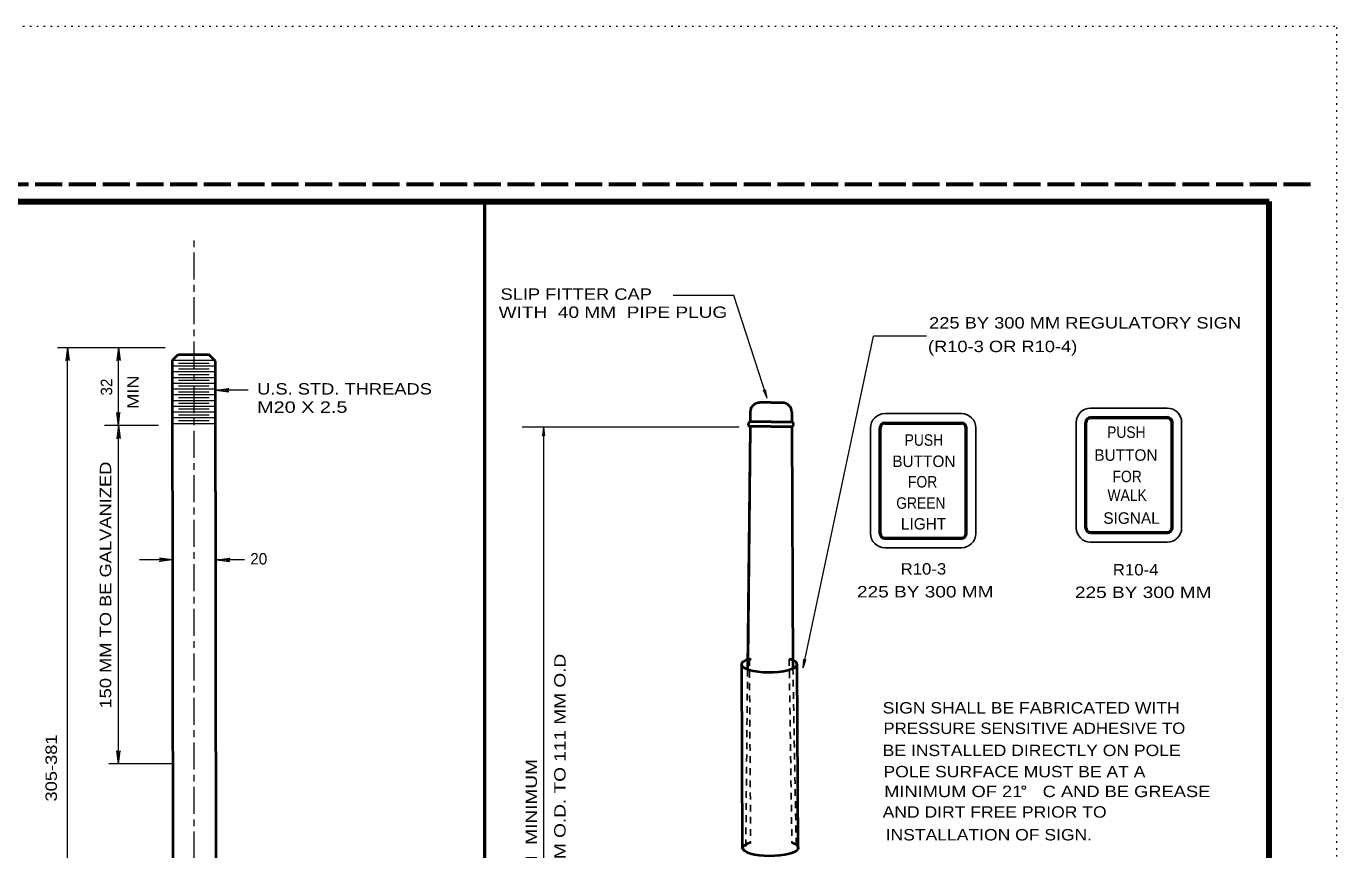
# Model space of a CAD drawing. Extents: x 312583 to 312854, y 144419 to 144597.
# Drawn here: x 312766.1 to 312853.5, y 144541.9 to 144596.8 of the extents above; entities that cross this region are included whole.
import ezdxf
from ezdxf.enums import TextEntityAlignment as Align

# ---------------------------------------------------------------- set-up
doc = ezdxf.new("R2010")
doc.units = 0
doc.header["$LTSCALE"] = 0.3
for name, pattern in [('DOTTED', [1.5, 0.3, -1.2]), ('LONG_DASH_SHORT_DASH', [9.9, 6, -1.2, 1.5, -1.2]), ('LONG_DASHED', [7.5, 6, -1.5]), ('SHORT_DASHED', [2.7, 1.5, -1.2])]:
    doc.linetypes.add(name, pattern=pattern)
for name, color, linetype, lineweight in [('1', 7, 'Continuous', 40), ('2', 7, 'Continuous', 13), ('62', 7, 'DOTTED', 13), ('63', 7, 'LONG_DASHED', 60)]:
    doc.layers.add(name, color=color, linetype=linetype, lineweight=lineweight)

msp = doc.modelspace()

# ---------------------------------------------------------------- linework, layer by layer
at = {"layer": '1', "lineweight": 53}
for p, q in [((312796.6723, 144460.1131), (312796.6723, 144585.0846)), ((312837.0869, 144570.6839), (312842.1929, 144570.6839)), ((312823.0385, 144562.9616), (312823.0385, 144569.9919)), ((312823.3605, 144570.3063), (312828.4741, 144570.3063)), ((312828.7885, 144562.9616), (312828.7885, 144569.9919)), ((312836.7649, 144563.3315), (312836.7649, 144570.3619)), ((312842.5149, 144563.3315), (312842.5149, 144570.3619)), ((312837.0869, 144563.0172), (312842.1929, 144563.0172)), ((312823.3605, 144562.6396), (312828.4741, 144562.6396))]:
    msp.add_line(p, q, dxfattribs=at)
at = {"layer": '1', "lineweight": 158}
msp.add_line((312849, 144423.1446), (312849, 144585.0846), dxfattribs=at)
at = {"layer": '1', "linetype": 'LONG_DASH_SHORT_DASH', "lineweight": 13}
msp.add_line((312777.2876, 144511.5796), (312777.2876, 144582.5116), dxfattribs=at)
at = {"layer": '1'}
for p, q in [((312775.8463, 144574.5153), (312776.2296, 144574.8986)), ((312775.9153, 144519.9976), (312775.8463, 144574.5153)), ((312776.2296, 144574.8986), (312778.269, 144574.8986)), ((312778.7213, 144574.4463), (312778.269, 144574.8986)), ((312778.7826, 144520.2276), (312778.7213, 144574.4463)), ((312815.7682, 144571.6786), (312815.0168, 144571.6786)), ((312815.7682, 144571.6786), (312816.5195, 144571.6786)), ((312814.3805, 144571.0423), (312814.3728, 144570.3906)), ((312817.1558, 144571.0423), (312817.1635, 144570.3906)), ((312814.3728, 144570.0839), (312814.2042, 144553.8766)), ((312814.3728, 144570.0839), (312814.2042, 144553.9609)), ((312814.3728, 144570.0839), (312814.2042, 144553.8996)), ((312814.3728, 144570.0839), (312814.2118, 144554.4593)), ((312815.7682, 144570.3983), (312814.3728, 144570.3983)), ((312815.7682, 144570.0839), (312814.3728, 144570.0839)), ((312815.7682, 144570.0839), (312814.3728, 144570.0839)), ((312815.7682, 144570.0839), (312814.3728, 144570.0839)), ((312815.7682, 144570.0839), (312814.3728, 144570.0839)), ((312815.7682, 144570.0839), (312814.3728, 144570.0839)), ((312815.7682, 144570.0839), (312814.3728, 144570.0839)), ((312815.7682, 144570.0839), (312814.3728, 144570.0839)), ((312815.7682, 144570.0839), (312814.3728, 144570.0839)), ((312815.7682, 144570.3983), (312817.1635, 144570.3983)), ((312815.7682, 144570.0839), (312817.1635, 144570.0839)), ((312815.7682, 144570.0839), (312817.1635, 144570.0839)), ((312815.7682, 144570.0839), (312817.1635, 144570.0839)), ((312815.7682, 144570.0839), (312817.1635, 144570.0839)), ((312815.7682, 144570.0839), (312817.1635, 144570.0839)), ((312815.7682, 144570.0839), (312817.1635, 144570.0839)), ((312815.7682, 144570.0839), (312817.1635, 144570.0839)), ((312815.7682, 144570.0839), (312817.1635, 144570.0839)), ((312817.1635, 144570.0839), (312817.2325, 144553.9993)), ((312813.7902, 144554.1679), (312813.8515, 144541.9089)), ((312814.3268, 144554.5819), (312814.4495, 144554.6049)), ((312817.0792, 144554.5589), (312816.9795, 144554.5743)), ((312817.4932, 144554.1833), (312817.5622, 144541.9396))]:
    msp.add_line(p, q, dxfattribs=at)
at = {"layer": '1', "lineweight": 13}
for p, q in [((312775.8463, 144574.5153), (312778.7213, 144574.5153)), ((312776.2526, 144574.3236), (312778.292, 144574.3236)), ((312775.8463, 144574.1319), (312778.7213, 144574.1319)), ((312775.8463, 144573.7486), (312778.7213, 144573.7486)), ((312775.8463, 144573.3653), (312778.7213, 144573.3653)), ((312776.2526, 144573.9403), (312778.292, 144573.9403)), ((312776.2526, 144573.5569), (312778.292, 144573.5569)), ((312775.8463, 144572.9819), (312778.7213, 144572.9819)), ((312775.8463, 144572.5986), (312778.7213, 144572.5986)), ((312776.2526, 144573.1736), (312778.292, 144573.1736)), ((312776.2526, 144572.7903), (312778.292, 144572.7903)), ((312775.8463, 144572.2153), (312778.7213, 144572.2153)), ((312775.8463, 144571.8319), (312778.7213, 144571.8319)), ((312776.2526, 144572.4069), (312778.292, 144572.4069)), ((312776.2526, 144572.0236), (312778.292, 144572.0236)), ((312776.2526, 144571.6403), (312778.292, 144571.6403)), ((312775.8463, 144571.4486), (312778.7213, 144571.4486)), ((312775.8463, 144571.0653), (312778.7213, 144571.0653)), ((312775.8463, 144570.6819), (312778.7213, 144570.6819)), ((312776.2526, 144571.2569), (312778.292, 144571.2569)), ((312776.2526, 144570.8736), (312778.292, 144570.8736)), ((312775.8463, 144570.2986), (312778.7213, 144570.2986)), ((312776.2526, 144570.4903), (312778.292, 144570.4903))]:
    msp.add_line(p, q, dxfattribs=at)
at = {"layer": '1', "lineweight": 25}
for p, q in [((312823.3605, 144570.9503), (312828.4741, 144570.9503)), ((312837.0869, 144571.3202), (312842.1929, 144571.3202)), ((312822.4021, 144562.9616), (312822.4021, 144569.9919)), ((312829.4325, 144562.9616), (312829.4325, 144569.9919)), ((312843.1512, 144563.3315), (312843.1512, 144570.3619)), ((312823.3605, 144562.0033), (312828.4741, 144562.0033)), ((312837.0869, 144562.3732), (312842.1929, 144562.3732))]:
    msp.add_line(p, q, dxfattribs=at)
at = {"layer": '1', "linetype": 'SHORT_DASHED', "lineweight": 25}
for p, q in [((312814.3268, 144554.5819), (312814.4112, 144542.3459)), ((312816.9795, 144554.5743), (312817.1635, 144542.3229)), ((312814.2042, 144553.8766), (312814.0815, 144541.7786)), ((312817.2325, 144553.9993), (312817.4548, 144541.7939))]:
    msp.add_line(p, q, dxfattribs=at)
at = {"layer": '1', "lineweight": 158}
msp.add_lwpolyline([(312616.5, 144423.1446), (312616.5, 144585.0846), (312849, 144585.0846)], dxfattribs=at)
at = {"layer": '1'}
for centre, start, end in [((312815.0188, 144571.0384), 90, 179.43048), ((312816.5162, 144571.0384), 0.56952, 90)]:
    msp.add_arc(centre, 0.6389, start, end, dxfattribs=at)
at = {"layer": '1', "lineweight": 25}
for centre, start, end in [((312823.3598, 144569.99), 90, 180), ((312828.4709, 144569.99), 0, 90), ((312837.0837, 144570.3612), 90, 180), ((312842.1948, 144570.3612), 0, 90), ((312823.3598, 144562.9622), 180, 270), ((312828.4709, 144562.9622), 270, 0), ((312837.0837, 144563.3335), 180, 270), ((312842.1948, 144563.3335), 270, 0)]:
    msp.add_arc(centre, 0.9583, start, end, dxfattribs=at)
at = {"layer": '1', "lineweight": 53}
for centre, start, end in [((312837.0837, 144570.3612), 90, 180), ((312842.1948, 144570.3612), 0, 90), ((312823.3598, 144569.99), 90, 180), ((312828.4709, 144569.99), 0, 90), ((312823.3598, 144562.9622), 180, 270), ((312828.4709, 144562.9622), 270, 0), ((312837.0837, 144563.3335), 180, 270), ((312842.1948, 144563.3335), 270, 0)]:
    msp.add_arc(centre, 0.3194, start, end, dxfattribs=at)
at = {"layer": '1'}
for centre in [(312815.6522, 144554.2219), (312815.7372, 144541.984)]:
    msp.add_ellipse(centre, major_axis=(1.8601, 0.0073), ratio=0.278719, start_param=2.3620161, end_param=6.9800621, dxfattribs=at)
at = {"layer": '2'}
for p, q in [((312813.2995, 144578.8163), (312809.2489, 144578.8163)), ((312815.5152, 144571.9776), (312813.2995, 144578.8163)), ((312817.9148, 144553.9916), (312822.5992, 144576.1176)), ((312826.1412, 144576.1176), (312822.5992, 144576.1176)), ((312768.1873, 144575.3509), (312770.058, 144575.3509)), ((312768.8543, 144575.3509), (312768.747, 144574.4846)), ((312768.8543, 144575.3509), (312768.747, 144574.4846)), ((312768.8543, 144517.3986), (312768.8543, 144575.3509)), ((312768.8543, 144575.3509), (312768.9616, 144574.4846)), ((312768.8543, 144575.3509), (312768.9616, 144574.4846)), ((312769.7513, 144575.3509), (312773.6613, 144575.3509)), ((312772.2506, 144575.3509), (312772.1433, 144574.4846)), ((312772.2506, 144575.3509), (312772.358, 144574.4846)), ((312772.2506, 144547.5976), (312772.2506, 144575.3279)), ((312773.6613, 144575.3509), (312775.3633, 144575.3509)), ((312768.747, 144574.4846), (312768.8543, 144574.7606)), ((312768.747, 144574.4846), (312768.8543, 144574.7606)), ((312768.9616, 144574.4846), (312768.8543, 144574.7606)), ((312768.9616, 144574.4846), (312768.8543, 144574.7606)), ((312772.1433, 144574.4846), (312772.2506, 144574.7606)), ((312772.358, 144574.4846), (312772.2506, 144574.7606)), ((312778.7443, 144572.5066), (312779.6106, 144572.6139)), ((312780.891, 144572.5066), (312778.7443, 144572.5066)), ((312778.7443, 144572.5066), (312779.6106, 144572.3993)), ((312779.6106, 144572.6139), (312779.3346, 144572.5066)), ((312779.6106, 144572.3993), (312779.3346, 144572.5066)), ((312815.2698, 144572.5066), (312815.3925, 144572.3533)), ((312815.5152, 144571.9776), (312815.2698, 144572.5066)), ((312815.2698, 144572.5066), (312815.3925, 144572.3533)), ((312815.5152, 144571.9776), (312815.2698, 144572.5066)), ((312815.4002, 144572.5449), (312815.3925, 144572.3533)), ((312815.4002, 144572.5449), (312815.3925, 144572.3533)), ((312815.5152, 144571.9776), (312815.4002, 144572.5449)), ((312815.5152, 144571.9776), (312815.4002, 144572.5449)), ((312772.1356, 144571.0269), (312772.243, 144570.7509)), ((312772.243, 144570.1606), (312772.1356, 144571.0269)), ((312772.3503, 144571.0269), (312772.243, 144570.7509)), ((312772.243, 144570.1606), (312772.3503, 144571.0269)), ((312772.2506, 144570.1529), (312772.1433, 144569.2866)), ((312772.2506, 144570.1529), (312772.358, 144569.2866)), ((312813.6522, 144570.0456), (312799.1641, 144570.0456)), ((312800.5894, 144570.0456), (312800.5204, 144569.4706)), ((312800.5894, 144570.0456), (312800.5894, 144506.8186)), ((312800.5894, 144570.0456), (312800.6661, 144569.4706)), ((312772.1433, 144569.2866), (312772.2506, 144569.5626)), ((312772.358, 144569.2866), (312772.2506, 144569.5626)), ((312800.5204, 144569.4706), (312800.5894, 144569.6546)), ((312800.6661, 144569.4706), (312800.5894, 144569.6546)), ((312775.8616, 144561.1983), (312773.6613, 144561.1983)), ((312774.9953, 144561.3056), (312775.2713, 144561.1983)), ((312775.8616, 144561.1983), (312774.9953, 144561.3056)), ((312774.9953, 144561.0909), (312775.2713, 144561.1983)), ((312775.8616, 144561.1983), (312774.9953, 144561.0909)), ((312778.8133, 144561.1983), (312779.6796, 144561.3056)), ((312778.8133, 144561.1983), (312779.6796, 144561.3056)), ((312780.6513, 144561.1983), (312778.8133, 144561.1983)), ((312778.8133, 144561.1983), (312779.6796, 144561.0909)), ((312778.8133, 144561.1983), (312779.6796, 144561.0909)), ((312779.6796, 144561.3056), (312779.4036, 144561.1983)), ((312779.6796, 144561.3056), (312779.4036, 144561.1983)), ((312779.6796, 144561.0909), (312779.4036, 144561.1983)), ((312779.6796, 144561.0909), (312779.4036, 144561.1983)), ((312817.9148, 144553.9916), (312817.9608, 144554.5666)), ((312817.9148, 144553.9916), (312818.0988, 144554.5359)), ((312817.9608, 144554.5666), (312817.9915, 144554.3749)), ((312818.0988, 144554.5359), (312817.9915, 144554.3749)), ((312772.1433, 144548.4639), (312772.2506, 144548.1879)), ((312772.2506, 144547.5976), (312772.1433, 144548.4639)), ((312772.358, 144548.4639), (312772.2506, 144548.1879)), ((312772.2506, 144547.5976), (312772.358, 144548.4639))]:
    msp.add_line(p, q, dxfattribs=at)
at = {"layer": '2', "lineweight": 25}
msp.add_line((312836.1286, 144570.3619), (312836.1286, 144563.3315), dxfattribs=at)
at = {"layer": '2'}
for points in [[(312774.9186, 144570.1453), (312773.6613, 144570.1453), (312771.323, 144570.1453)], [(312775.8463, 144547.5976), (312773.6613, 144547.5976), (312771.6066, 144547.5976)]]:
    msp.add_lwpolyline(points, dxfattribs=at)
msp.add_circle((312832.6282, 144546.0069), 0.1198, dxfattribs=at)
at = {"layer": '2', "lineweight": 40}
for centre, radius, start, end in [((312814.4162, 144570.2398), 0.1662, 106.02508, 253.97491), ((312817.1021, 144570.241), 0.1704, 251.43821, 68.43038)]:
    msp.add_arc(centre, radius, start, end, dxfattribs=at)
at = {"layer": '62'}
msp.add_line((312601.2, 144596.7846), (312853.5, 144596.7846), dxfattribs=at)
msp.add_lwpolyline([(312601.2, 144418.5846), (312853.5, 144418.5846), (312853.5, 144596.7846)], dxfattribs=at)
at = {"layer": '63'}
msp.add_line((312851.75, 144586.2246), (312583.526, 144586.2246), dxfattribs=at)

# ---------------------------------------------------------------- texts
at = {"layer": '2'}
for s, width, p in [('SLIP FITTER CAP', 1.2, (312797.7285, 144578.5391)), ('WITH  40 MM  PIPE PLUG', 1.25, (312797.6019, 144577.3317)), ('225 BY 300 MM REGULATORY SIGN', 1.2, (312826.3098, 144576.6226)), ('(R10-3 OR R10-4)', 1.2, (312826.2332, 144575.0509)), ('U.S. STD. THREADS', 1.2, (312781.4985, 144572.22)), ('M20 X 2.5', 1.3, (312781.4985, 144571)), ('R10-3', 1.1, (312824.4096, 144560.2141)), ('R10-4', 1.1, (312838.5634, 144560.1565)), ('225 BY 300 MM', 1.25, (312821.4999, 144558.6903)), ('225 BY 300 MM', 1.25, (312836.0354, 144558.6501)), ('SIGN SHALL BE FABRICATED WITH', 1.15, (312823.2148, 144550.9469)), ('PRESSURE SENSITIVE ADHESIVE TO', 1.1, (312823.2685, 144549.5823)), ('BE INSTALLED DIRECTLY ON POLE', 1.15, (312823.2148, 144548.1103)), ('POLE SURFACE MUST BE AT A', 1.15, (312823.2685, 144546.6919)), ('MINIMUM OF 21    C AND BE GREASE', 1.2, (312823.3145, 144545.3733)), ('AND DIRT FREE PRIOR TO', 1.15, (312823.2148, 144544.0009)), ('INSTALLATION OF SIGN.', 1.15, (312823.4141, 144542.4829))]:
    msp.add_text(s, height=0.76, dxfattribs=dict(at, width=width)).set_placement(p)
for s, width, p in [(' MIN', 1.2, (312773.6035, 144570.9238)), ('150 MM TO BE GALVANIZED', 1.2, (312771.7651, 144551.2792)), ('TAPER - 152 MM O.D. TO 111 MM O.D', 1.25, (312802.0686, 144532.3434)), ('305-381 ', 1.2, (312768.1446, 144545.0767)), ('2.5 M  MINIMUM', 1.25, (312800.1596, 144538.3103))]:
    msp.add_text(s, height=0.76, rotation=90, dxfattribs=dict(at, width=width)).set_placement(p)
msp.add_text('32', height=0.76, rotation=90, dxfattribs=at).set_placement((312771.8322, 144572.1527))
at = {"layer": '2', "width": 0.9}
for s, p in [('PUSH', (312839.4673, 144569.3269)), ('PUSH', (312825.9633, 144568.8036)), ('FOR', (312825.879, 144566.0206)), ('FOR', (312839.5211, 144566.3752)), ('WALK', (312839.5173, 144565.1255)), ('GREEN', (312825.7601, 144564.6023))]:
    msp.add_text(s, height=0.7666, dxfattribs=at).set_placement(p, align=Align.CENTER)
at = {"layer": '2'}
for s, p in [('BUTTON', (312825.9633, 144567.3853)), ('BUTTON', (312839.4367, 144567.8012)), ('LIGHT', (312825.9403, 144563.2146)), ('SIGNAL', (312839.8124, 144563.5999))]:
    msp.add_text(s, height=0.7666, dxfattribs=at).set_placement(p, align=Align.CENTER)
msp.add_text('20', height=0.76, dxfattribs=at).set_placement((312781.0408, 144560.8868))

doc.saveas('drawing.dxf')
